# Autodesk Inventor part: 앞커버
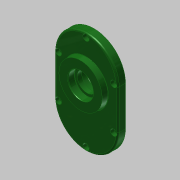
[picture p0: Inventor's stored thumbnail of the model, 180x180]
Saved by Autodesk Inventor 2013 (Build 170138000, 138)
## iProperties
Created: 2016-12
Part Number: 앞커버
Material: 알루미늄 6061
Document SubType Name: Modeling
Designer: mduedu
Density: 2.71 g/cm^3
Mass: 264.671 g
Surface Area: 264.413 cm^2
Volume: 97.6646 cm^3
Author: mduedu
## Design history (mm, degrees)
sketch "스케치1"
  geometry: L1 (40, -25)-(40, 25); L2 (-40, 25)-(-40, -25); L3 (-40, -25)-(40, 25); L4 (40, -25)-(-40, 25); A1 r 40 centre (0, 25) between (40, 25) and (-40, 25); A2 r 40 centre (0, -25) between (-40, -25) and (40, -25); 1 further point
  constraints: 8 end point, 4 point on circle, 4 tangent, 2 centre point, 2 midpoint, 1 parallel, 1 vertical
  dimensions: "d0" = 130 dimension on A2 A1; "d2" = 80 distance between parallel lines of L1 L2
extrude "돌출1" new body sketch "스케치1" distance "d3" = 10; taper "d4" = 0 deg
sketch "스케치2"
  geometry: C1 r 21 at (0, 11); 1 further point
  constraints: 1 centre point, 1 vertical alignment
  dimensions: "d5" = 42 diameter of C1; "d7" = 11 distance of C1.centre point (0, 0)
extrude "돌출2" join sketch "스케치2" distance "d8" = 7; taper "d9" = 0 deg
sketch "스케치3"
  geometry: C1 r 15 at (0, -33.1); C2 r 21 at (0, 11) reference; 1 further point
  constraints: 1 centre point, 1 vertical alignment
  dimensions: "d10" = 30 diameter of C1; "d71" = 44.1 distance of C1.centre C2.centre
extrude "돌출3" join sketch "스케치3" distance "d12" = 7; taper "d13" = 0 deg
sketch "스케치4"
  geometry: C1 r 28 at (0, 11); A1 r 21 centre (0, 11) between (8.978, -7.984) and (-8.978, -7.984) reference; 1 further point
  constraints: 1 centre point, 1 coincident
  dimensions: "d14" = 56 diameter of C1
extrude "돌출4" join sketch "스케치4" distance "d15" = 7; taper "d16" = -5 deg
hole "구멍1" diameter "d19" = 35; stored, may be unused: countersink angle "d23" = 90 deg, drill point angle "d25" = 0 deg; dims "d17" = 10, "d18" = 10, "d20" = 6, "d21" = 4, "d22" = 2, "d24" = 10
hole "구멍2" diameter "d28" = 22; stored, may be unused: countersink angle "d32" = 90 deg, drill point angle "d34" = 0 deg; dims "d26" = 10, "d27" = 10, "d29" = 6, "d30" = 4, "d31" = 2, "d33" = 7
hole "구멍3" diameter "d37" = 19; stored, may be unused: countersink angle "d41" = 90 deg, drill point angle "d43" = 0 deg; dims "d35" = 10, "d36" = 10, "d38" = 6, "d39" = 4, "d40" = 2, "d42" = 1
hole "구멍4" diameter "d46" = 32; stored, may be unused: countersink angle "d50" = 90 deg, drill point angle "d52" = 0 deg; dims "d47" = 6, "d48" = 4, "d49" = 2, "d51" = 8.3, "d89" = 10, "d90" = 10
hole "구멍5" diameter "d55" = 25; stored, may be unused: countersink angle "d59" = 90 deg, drill point angle "d61" = 0 deg; dims "d53" = 10, "d54" = 10, "d56" = 6, "d57" = 4, "d58" = 2, "d60" = 8
fillet "모깎기1" dims "d62" = 0.3
fillet "모깎기2" dims "d63" = 2
chamfer "모따기1" distance "d64" = 1; stored, may be unused: second distance "d65" = 2, angle "d66" = 45 deg
chamfer "모따기2" distance "d91" = 0.8; stored, may be unused: second distance "d92" = 2, angle "d93" = 30 deg
fillet "모깎기4" dims "d68" = 2
fillet "모깎기5" dims "d69" = 0.3
fillet "모깎기6" dims "d70" = 2
sketch "스케치5"
  geometry: L1 (-40, 25)-(-40, -25) reference; L2 (40, -25)-(40, 25) reference; L3 (35, 25)-(35, -25); L4 (-35, -25)-(-35, 25); A1 r 40 centre (0, 25) between (40, 25) and (-40, 25) reference; A2 r 40 centre (0, -25) between (-40, -25) and (40, -25) reference; A3 r 35 centre (0, 25) between (35, 25) and (-35, 25); A4 r 35 centre (0, -25) between (-35, -25) and (35, -25); 2 further points
  constraints: 5 point on circle, 4 end point, 2 centre point, 1 vertical alignment, 3 other
  dimensions: "d72" = 5 distance between parallel lines of L2 L3
sketch "스케치7"
  geometry: 1 further point
  constraints: 1 other
hole "구멍7" sketch "스케치7" at (0, 60) diameter "d80" = 4.5; stored, may be unused: countersink angle "d84" = 90 deg, drill point angle "d86" = 0 deg; dims "d81" = 6, "d82" = 8, "d83" = 4.6, "d85" = 8
node "솔리드1"
pattern_linear "직사각형 패턴1"
